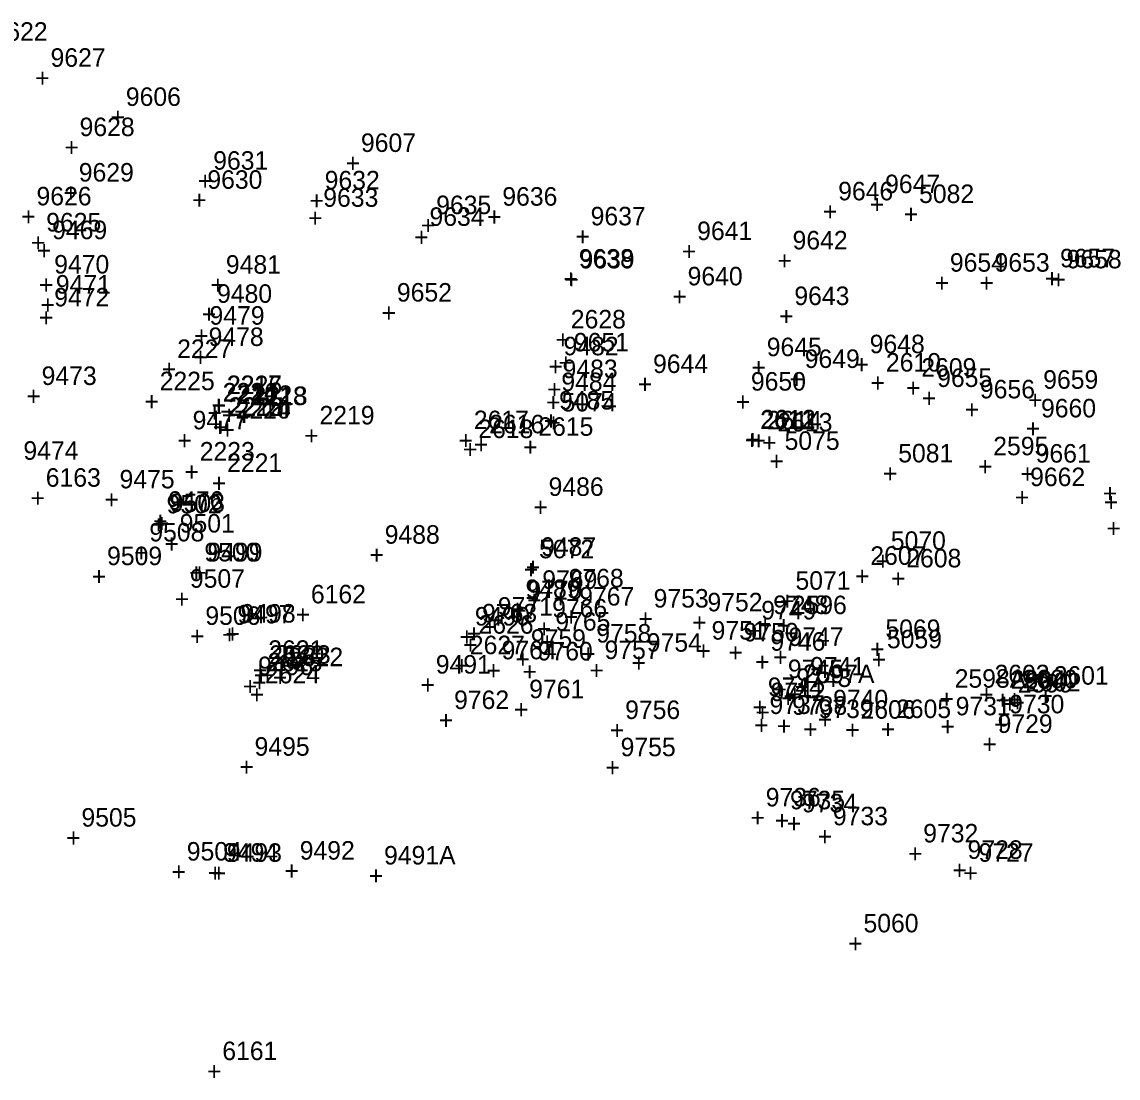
# Model space of a CAD drawing. Extents: x 1136220 to 1137808, y 528804 to 531215.
# Drawn here: x 1136639.3 to 1136787.3, y 529144.3 to 529287 of the extents above; entities that cross this region are included whole.
import ezdxf

# ---------------------------------------------------------------- set-up
doc = ezdxf.new("R2010")
doc.units = 0
for name, color, linetype in [('S_Buildings', 7, 'Continuous'), ('S_Curb_Type_3', 7, 'Continuous'), ('S_Drainage_CB', 7, 'Continuous'), ('S_Drainage_Culvert_Top', 7, 'Continuous'), ('S_Drainage_Invert', 7, 'Continuous'), ('S_Drainage_RipRap', 7, 'Continuous'), ('S_Drainage_Sump', 7, 'Continuous'), ('S_Ground_Elevation', 7, 'Continuous'), ('S_Ground_LevelString', 7, 'Continuous'), ('S_Railroad_Signal', 7, 'Continuous'), ('S_Railroad_Tracks', 7, 'Continuous'), ('S_Roadway_Centerline', 7, 'Continuous'), ('S_Roadway_Drive_Gravel', 7, 'Continuous'), ('S_Roadway_Drive_Paved', 7, 'Continuous'), ('S_Roadway_Edge_Pavement', 7, 'Continuous'), ('S_Roadway_Sidewalks', 7, 'Continuous'), ('S_Trees_TreeLine', 7, 'Continuous'), ('S_Utilities_Pole_Joint', 7, 'Continuous'), ('S_Utilities_UG_Gas_Line', 7, 'Continuous'), ('S_Utilities_UG_Sanitary_MH', 7, 'Continuous'), ('S_Utilities_UG_Water_Gate', 7, 'Continuous')]:
    doc.layers.add(name, color=color, linetype=linetype)

msp = doc.modelspace()

# ---------------------------------------------------------------- texts
at = {"layer": 'S_Buildings'}
for s, p in [('9606', (1136653.3, 529275.66)), ('+', (1136651.24, 529272.91)), ('9607', (1136685.06, 529269.44)), ('+', (1136683, 529266.69))]:
    msp.add_text(s, height=2.5, dxfattribs=at).set_placement(p)
at = {"layer": 'S_Curb_Type_3'}
for s, p in [('9502', (1136658.8, 529220.6)), ('+', (1136656.74, 529217.85)), ('9501', (1136660.58, 529218.01)), ('+', (1136658.52, 529215.26)), ('9500', (1136663.9, 529214.11)), ('+', (1136661.84, 529211.36)), ('9497', (1136668.38, 529205.73)), ('+', (1136666.32, 529202.98)), ('9496', (1136671.17, 529198.74)), ('+', (1136669.11, 529195.99)), ('9494', (1136666.44, 529173.53)), ('+', (1136664.38, 529170.78))]:
    msp.add_text(s, height=2.5, dxfattribs=at).set_placement(p)
at = {"layer": 'S_Drainage_CB'}
for s, p in [('2611', (1136738.98, 529232)), ('+', (1136736.92, 529229.25)), ('2620', (1136672.66, 529200.26)), ('+', (1136670.6, 529197.51)), ('2599', (1136773.8, 529196.39)), ('+', (1136771.74, 529193.64))]:
    msp.add_text(s, height=2.5, dxfattribs=at).set_placement(p)
at = {"layer": 'S_Drainage_Culvert_Top'}
for s, p in [('2227', (1136660.23, 529241.6)), ('+', (1136658.17, 529238.85)), ('2225', (1136657.87, 529237.24)), ('2226', (1136666.98, 529236.71)), ('2224', (1136666.38, 529235.72)), ('2218', (1136670.3, 529235.22)), ('+', (1136655.81, 529234.49)), ('+', (1136664.91, 529233.96)), ('2222', (1136667.12, 529233.76)), ('2220', (1136668.13, 529233.41)), ('+', (1136664.32, 529232.98)), ('+', (1136668.24, 529232.47)), ('2219', (1136679.46, 529232.62)), ('2613', (1136741.32, 529231.67)), ('+', (1136665.05, 529231.01)), ('+', (1136666.07, 529230.66)), ('+', (1136677.4, 529229.87)), ('2223', (1136663.28, 529227.74)), ('+', (1136739.26, 529228.92)), ('2221', (1136666.98, 529226.2)), ('+', (1136661.22, 529224.99)), ('+', (1136664.91, 529223.45)), ('2622', (1136675.22, 529199.95)), ('2624', (1136672.09, 529197.63)), ('2597A', (1136744.77, 529197.66)), ('2603', (1136770.65, 529197.64)), ('+', (1136673.16, 529197.2)), ('2598A', (1136765.27, 529197.04)), ('2601', (1136778.64, 529197.45)), ('+', (1136670.03, 529194.88)), ('+', (1136742.71, 529194.91)), ('+', (1136763.21, 529194.29)), ('+', (1136768.58, 529194.89)), ('+', (1136776.58, 529194.7))]:
    msp.add_text(s, height=2.5, dxfattribs=at).set_placement(p)
at = {"layer": 'S_Drainage_Invert'}
for s, p in [('2217', (1136666.93, 529236.73)), ('2216', (1136666.4, 529235.71)), ('2213', (1136670.41, 529235.25)), ('+', (1136664.87, 529233.98)), ('2215', (1136667.21, 529233.78)), ('2214', (1136668.12, 529233.43)), ('+', (1136664.34, 529232.96)), ('+', (1136668.35, 529232.5)), ('2614', (1136739.88, 529231.95)), ('+', (1136665.15, 529231.03)), ('+', (1136666.06, 529230.68)), ('+', (1136737.82, 529229.2)), ('2625', (1136672.44, 529199.26)), ('2623', (1136673.53, 529200.28)), ('2597', (1136744.77, 529197.67)), ('+', (1136670.37, 529196.51)), ('+', (1136671.47, 529197.53)), ('2598', (1136765.27, 529197.04)), ('2604', (1136772.83, 529196.89)), ('2602', (1136774.85, 529196.55)), ('+', (1136742.71, 529194.92)), ('+', (1136763.21, 529194.29)), ('+', (1136770.77, 529194.14)), ('+', (1136772.79, 529193.8))]:
    msp.add_text(s, height=2.5, dxfattribs=at).set_placement(p)
at = {"layer": 'S_Drainage_RipRap'}
for s, p in [('9769', (1136709.56, 529210.4)), ('9768', (1136713.12, 529210.6)), ('9770', (1136707.54, 529209)), ('9767', (1136714.55, 529208.14)), ('9771', (1136703.55, 529206.78)), ('+', (1136707.5, 529207.65)), ('9766', (1136710.89, 529206.53)), ('+', (1136711.06, 529207.85)), ('9763', (1136701.42, 529205.87)), ('+', (1136705.48, 529206.25)), ('+', (1136712.48, 529205.39)), ('+', (1136701.49, 529204.03)), ('9765', (1136711.32, 529204.75)), ('+', (1136699.36, 529203.12)), ('+', (1136708.83, 529203.78)), ('9764', (1136704.06, 529200.88)), ('+', (1136709.25, 529202)), ('+', (1136702, 529198.13))]:
    msp.add_text(s, height=2.5, dxfattribs=at).set_placement(p)
at = {"layer": 'S_Drainage_Sump'}
for s, p in [('2612', (1136739.06, 529232.09)), ('+', (1136737, 529229.34)), ('2621', (1136672.53, 529200.94)), ('+', (1136670.46, 529198.19)), ('2600', (1136774.44, 529196.96)), ('+', (1136772.38, 529194.21))]:
    msp.add_text(s, height=2.5, dxfattribs=at).set_placement(p)
at = {"layer": 'S_Ground_Elevation'}
for s, p in [('9628', (1136647.05, 529271.58)), ('+', (1136644.99, 529268.83)), ('9631', (1136665.1, 529267.04)), ('9629', (1136646.94, 529265.44)), ('9630', (1136664.31, 529264.46)), ('9632', (1136680.16, 529264.38)), ('+', (1136663.04, 529264.29)), ('9647', (1136755.87, 529263.87)), ('+', (1136644.88, 529262.69)), ('+', (1136662.25, 529261.71)), ('+', (1136678.1, 529261.63)), ('9633', (1136679.97, 529262.03)), ('9636', (1136704.16, 529262.18)), ('9635', (1136695.22, 529261.04)), ('+', (1136753.81, 529261.12)), ('+', (1136677.91, 529259.28)), ('9634', (1136694.32, 529259.45)), ('+', (1136702.1, 529259.43)), ('9637', (1136716.09, 529259.52)), ('+', (1136693.16, 529258.29)), ('9641', (1136730.48, 529257.53)), ('+', (1136692.26, 529256.7)), ('+', (1136714.03, 529256.77)), ('9642', (1136743.37, 529256.27)), ('9638', (1136714.49, 529253.81)), ('+', (1136728.41, 529254.78)), ('9657', (1136779.5, 529253.85)), ('+', (1136741.31, 529253.52)), ('9654', (1136764.62, 529253.26)), ('9653', (1136770.66, 529253.26)), ('9640', (1136729.19, 529251.41)), ('+', (1136712.43, 529251.06)), ('+', (1136762.56, 529250.51)), ('+', (1136768.6, 529250.51)), ('+', (1136777.44, 529251.1)), ('9652', (1136689.92, 529249.22)), ('+', (1136727.13, 529248.66)), ('9643', (1136743.61, 529248.75)), ('+', (1136687.85, 529246.47)), ('+', (1136741.55, 529246)), ('9651', (1136713.82, 529242.48)), ('9648', (1136753.79, 529242.24)), ('+', (1136711.76, 529239.73)), ('9649', (1136745.01, 529240.25)), ('+', (1136751.73, 529239.49)), ('9655', (1136762.9, 529237.68)), ('9650', (1136737.74, 529237.19)), ('+', (1136742.95, 529237.5)), ('9656', (1136768.68, 529236.14)), ('+', (1136735.68, 529234.44)), ('+', (1136760.84, 529234.93)), ('+', (1136766.62, 529233.39)), ('9508', (1136656.47, 529216.81)), ('9509', (1136650.76, 529213.6)), ('+', (1136654.41, 529214.06)), ('+', (1136648.7, 529210.85)), ('9507', (1136661.95, 529210.55)), ('+', (1136659.89, 529207.8)), ('9753', (1136724.6, 529207.87)), ('9752', (1136731.87, 529207.36)), ('9748', (1136740.75, 529207)), ('9506', (1136664.04, 529205.53)), ('9749', (1136739.14, 529206.27)), ('+', (1136722.54, 529205.12)), ('+', (1136729.81, 529204.61)), ('9751', (1136732.43, 529203.54)), ('+', (1136738.69, 529204.25)), ('+', (1136661.97, 529202.78)), ('9759', (1136708.02, 529202.43)), ('9758', (1136716.85, 529203.14)), ('9750', (1136736.75, 529203.3)), ('+', (1136737.08, 529203.52)), ('9746', (1136740.37, 529202.04)), ('9747', (1136742.82, 529202.68)), ('9760', (1136708.94, 529200.73)), ('9757', (1136717.97, 529200.91)), ('9754', (1136723.68, 529201.91)), ('+', (1136705.95, 529199.68)), ('+', (1136714.78, 529200.39)), ('+', (1136730.36, 529200.79)), ('+', (1136734.69, 529200.55)), ('+', (1136740.76, 529199.93)), ('+', (1136706.88, 529197.98)), ('+', (1136715.91, 529198.16)), ('+', (1136721.61, 529199.16)), ('+', (1136738.31, 529199.29)), ('9745', (1136742.74, 529198.34)), ('9741', (1136745.75, 529198.69)), ('9743', (1136743.87, 529197.14)), ('9761', (1136707.79, 529195.62)), ('9744', (1136740.03, 529195.92)), ('9742', (1136740.4, 529195.23)), ('+', (1136740.67, 529195.59)), ('+', (1136743.68, 529195.94)), ('9762', (1136697.64, 529194.16)), ('9737', (1136740.25, 529193.49)), ('+', (1136741.81, 529194.39)), ('9738', (1136743.31, 529193.38)), ('9740', (1136748.85, 529194.26)), ('9731', (1136765.4, 529193.31)), ('+', (1136705.73, 529192.87)), ('9756', (1136720.75, 529192.81)), ('+', (1136737.97, 529193.17)), ('+', (1136738.34, 529192.48)), ('9739', (1136746.88, 529192.94)), ('+', (1136695.58, 529191.41)), ('+', (1136738.19, 529190.74)), ('+', (1136741.24, 529190.63)), ('+', (1136746.79, 529191.51)), ('+', (1136763.34, 529190.56)), ('9729', (1136771.07, 529190.93)), ('+', (1136718.69, 529190.06)), ('+', (1136744.81, 529190.19)), ('9755', (1136720.14, 529187.78)), ('+', (1136769.01, 529188.18)), ('+', (1136718.08, 529185.03)), ('9736', (1136739.74, 529181)), ('9735', (1136743.02, 529180.61)), ('9734', (1136744.64, 529180.2)), ('9505', (1136647.3, 529178.27)), ('9733', (1136748.82, 529178.45)), ('+', (1136737.68, 529178.25)), ('+', (1136740.96, 529177.86)), ('+', (1136742.58, 529177.45)), ('9732', (1136761.02, 529176.13)), ('+', (1136645.24, 529175.52)), ('+', (1136746.76, 529175.7)), ('9728', (1136767.01, 529173.91)), ('9504', (1136661.53, 529173.68)), ('+', (1136758.96, 529173.38)), ('+', (1136659.47, 529170.94)), ('+', (1136764.95, 529171.16))]:
    msp.add_text(s, height=2.5, dxfattribs=at).set_placement(p)
at = {"layer": 'S_Ground_LevelString'}
for s, p in [('9470', (1136643.62, 529253.01)), ('+', (1136641.56, 529250.26)), ('9471', (1136643.84, 529250.3)), ('9480', (1136665.62, 529249.05)), ('+', (1136641.78, 529247.55)), ('+', (1136663.56, 529246.3)), ('9479', (1136664.6, 529246.1)), ('+', (1136662.54, 529243.35)), ('9483', (1136712.3, 529238.88)), ('9484', (1136712.13, 529237.12)), ('+', (1136710.23, 529236.13)), ('+', (1136710.07, 529234.37))]:
    msp.add_text(s, height=2.5, dxfattribs=at).set_placement(p)
at = {"layer": 'S_Railroad_Signal'}
for s, p in [('2595', (1136770.48, 529228.45)), ('+', (1136768.42, 529225.7)), ('2596', (1136743.26, 529206.98)), ('+', (1136741.19, 529204.23))]:
    msp.add_text(s, height=2.5, dxfattribs=at).set_placement(p)
at = {"layer": 'S_Railroad_Tracks'}
for s, p in [('2610', (1136755.98, 529239.76)), ('2609', (1136760.76, 529239.07)), ('+', (1136753.91, 529237.01)), ('+', (1136758.7, 529236.32)), ('2607', (1136753.87, 529213.64)), ('2608', (1136758.73, 529213.3)), ('+', (1136751.81, 529210.89)), ('+', (1136756.67, 529210.55)), ('2606', (1136752.55, 529192.85)), ('2605', (1136757.35, 529192.94)), ('+', (1136750.49, 529190.1)), ('+', (1136755.29, 529190.19))]:
    msp.add_text(s, height=2.5, dxfattribs=at).set_placement(p)
at = {"layer": 'S_Roadway_Centerline'}
for s, p in [('5082', (1136760.46, 529262.54)), ('+', (1136758.4, 529259.79)), ('9473', (1136641.92, 529237.95)), ('+', (1136639.86, 529235.2)), ('9477', (1136662.32, 529231.96)), ('+', (1136660.26, 529229.21)), ('9486', (1136710.41, 529222.96)), ('+', (1136708.35, 529220.21)), ('9488', (1136688.27, 529216.5)), ('5070', (1136756.64, 529215.67)), ('+', (1136686.21, 529213.75)), ('+', (1136754.58, 529212.92)), ('5069', (1136755.91, 529203.76)), ('+', (1136753.85, 529201.01)), ('9492', (1136676.79, 529173.81)), ('+', (1136674.73, 529171.06)), ('5060', (1136752.95, 529163.98)), ('+', (1136750.89, 529161.23))]:
    msp.add_text(s, height=2.5, dxfattribs=at).set_placement(p)
at = {"layer": 'S_Roadway_Drive_Gravel'}
for s, p in [('9622', (1136635.29, 529284.47)), ('9627', (1136643.13, 529280.95)), ('+', (1136641.06, 529278.2)), ('9626', (1136641.23, 529262.22)), ('+', (1136639.17, 529259.47)), ('9625', (1136642.54, 529258.7)), ('+', (1136640.48, 529255.95))]:
    msp.add_text(s, height=2.5, dxfattribs=at).set_placement(p)
at = {"layer": 'S_Roadway_Drive_Paved'}
for s, p in [('9658', (1136780.39, 529253.71)), ('+', (1136778.33, 529250.96)), ('9659', (1136777.23, 529237.44)), ('+', (1136775.17, 529234.69)), ('9660', (1136776.93, 529233.57)), ('+', (1136774.87, 529230.82)), ('9661', (1136776.21, 529227.46)), ('+', (1136774.14, 529224.71)), ('9662', (1136775.46, 529224.28)), ('+', (1136785.27, 529222.07)), ('+', (1136773.4, 529221.53)), ('+', (1136785.42, 529220.87)), ('+', (1136785.76, 529217.35)), ('9730', (1136772.64, 529193.58)), ('+', (1136770.58, 529190.83)), ('9727', (1136768.49, 529173.52)), ('+', (1136766.43, 529170.77))]:
    msp.add_text(s, height=2.5, dxfattribs=at).set_placement(p)
at = {"layer": 'S_Roadway_Edge_Pavement'}
for s, p in [('9472', (1136643.62, 529248.57)), ('+', (1136641.56, 529245.82)), ('9478', (1136664.48, 529243.22)), ('+', (1136662.42, 529240.47)), ('9485', (1136711.82, 529234.63)), ('5074', (1136712.16, 529234.37)), ('+', (1136709.76, 529231.88)), ('+', (1136710.1, 529231.62)), ('5075', (1136742.29, 529229.18)), ('9474', (1136639.46, 529227.84)), ('5081', (1136757.64, 529227.49)), ('+', (1136740.23, 529226.43)), ('+', (1136755.58, 529224.74)), ('9475', (1136652.45, 529223.98)), ('+', (1136650.39, 529221.23)), ('9476', (1136659.05, 529221.09)), ('9503', (1136659.25, 529220.78)), ('+', (1136656.98, 529218.34)), ('+', (1136657.19, 529218.03)), ('9499', (1136664.32, 529214.11)), ('5072', (1136709.12, 529214.53)), ('9487', (1136709.39, 529214.86)), ('+', (1136662.26, 529211.36)), ('+', (1136707.06, 529211.78)), ('+', (1136707.33, 529212.11)), ('5071', (1136743.76, 529210.28)), ('9489', (1136707.29, 529209.17)), ('+', (1136741.69, 529207.53)), ('9498', (1136668.8, 529205.84)), ('9490', (1136700.45, 529205.44)), ('+', (1136705.23, 529206.42)), ('+', (1136666.74, 529203.09)), ('+', (1136698.39, 529202.69)), ('5059', (1136756.12, 529202.37)), ('+', (1136754.06, 529199.62)), ('9491', (1136695.17, 529198.95)), ('+', (1136693.11, 529196.2)), ('9495', (1136670.69, 529187.85)), ('+', (1136668.63, 529185.1)), ('9493', (1136666.95, 529173.51)), ('9491A', (1136688.18, 529173.15)), ('+', (1136664.89, 529170.76)), ('+', (1136686.12, 529170.4))]:
    msp.add_text(s, height=2.5, dxfattribs=at).set_placement(p)
at = {"layer": 'S_Roadway_Sidewalks'}
for s, p in [('9469', (1136643.34, 529257.65)), ('+', (1136641.28, 529254.9)), ('9481', (1136666.81, 529252.99)), ('+', (1136664.75, 529250.24)), ('9482', (1136712.43, 529241.96)), ('+', (1136710.37, 529239.21))]:
    msp.add_text(s, height=2.5, dxfattribs=at).set_placement(p)
at = {"layer": 'S_Trees_TreeLine'}
for s, p in [('9646', (1136749.53, 529262.9)), ('+', (1136747.47, 529260.15)), ('9639', (1136714.59, 529253.7)), ('+', (1136712.53, 529250.95)), ('9645', (1136739.88, 529241.84)), ('9644', (1136724.52, 529239.57)), ('+', (1136737.82, 529239.09)), ('+', (1136722.46, 529236.82))]:
    msp.add_text(s, height=2.5, dxfattribs=at).set_placement(p)
at = {"layer": 'S_Utilities_Pole_Joint'}
for s, p in [('2628', (1136713.41, 529245.59)), ('+', (1136711.35, 529242.84)), ('2626', (1136700.94, 529204.34)), ('+', (1136698.88, 529201.59)), ('2627', (1136699.77, 529201.57)), ('+', (1136697.71, 529198.82))]:
    msp.add_text(s, height=2.5, dxfattribs=at).set_placement(p)
at = {"layer": 'S_Utilities_UG_Gas_Line'}
for s, p in [('6163', (1136642.48, 529224.2)), ('+', (1136640.42, 529221.45)), ('6162', (1136678.3, 529208.44)), ('+', (1136676.24, 529205.69)), ('6161', (1136666.33, 529146.72)), ('+', (1136664.27, 529143.97))]:
    msp.add_text(s, height=2.5, dxfattribs=at).set_placement(p)
at = {"layer": 'S_Utilities_UG_Sanitary_MH'}
for s, p in [('2212', (1136668.34, 529235.39)), ('+', (1136666.28, 529232.64))]:
    msp.add_text(s, height=2.5, dxfattribs=at).set_placement(p)
at = {"layer": 'S_Utilities_UG_Water_Gate'}
for s, p in [('2617', (1136700.31, 529231.98)), ('2618', (1136700.91, 529230.77)), ('2616', (1136702.38, 529231.42)), ('2615', (1136709.02, 529231.08)), ('+', (1136698.25, 529229.23)), ('+', (1136698.84, 529228.02)), ('+', (1136700.32, 529228.67)), ('+', (1136706.96, 529228.33))]:
    msp.add_text(s, height=2.5, dxfattribs=at).set_placement(p)

doc.saveas('drawing.dxf')
